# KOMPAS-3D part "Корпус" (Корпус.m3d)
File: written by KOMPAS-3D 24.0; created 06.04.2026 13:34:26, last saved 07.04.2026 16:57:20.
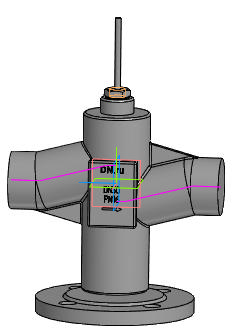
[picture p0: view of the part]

Document properties: Автор: R2D2; Полное имя файла: E:\Работа\Зайцев\Солянка\VSR1-13V-PED-F Клапан запорно-регулирующий DN.ru\DN50\исходные материалы\Корпус.m3d

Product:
- Body: Труба / Нестандартная труба / L = 112.5 мм  | qty 1
    Материал: Нестандартная труба (density 7856 kg/m3)
    Масса: 9.621901
    Раздел спецификации: Детали
    Примечание: 2,5 кг
    additional columns: Pipeline; 0.06; 0; 0; 0.002; 0.11245; true; 0.04
- Body: Труба / Нестандартная труба / L = 112.5 мм  | qty 1
    Материал: Нестандартная труба (density 7856 kg/m3)
    Масса: 9.621901
    Раздел спецификации: Детали
    Форматы листов документа: БЧ
    Примечание: 2,5 кг
    additional columns: Pipeline; 0.06; 0; 0; 0.002; 0.11245; true; 0.04
- Component [standard]: Гайка М16-6H ГОСТ 5916-70  | qty 1  | Масса: 0.01768; Рассекать на разрезах: no; source file: C:\Program Files\ASCON\KOMPAS-3D v24\Libs\PolynomLib\DATA\vault\Methods\Kompas\3D\PLib_Nut_OST92_900.m3d
- Component [standard]: (unnamed)  | qty 1  | Материал: ВЧ40 ГОСТ 7293-85 (density 7200 kg/m3); Масса: 2.386453; Рассекать на разрезах: no; additional columns: 50-16-B-2-ВЧ40-II; Заглушка; ГОСТ 34785-2021
- Body: Тело 4  | qty 1
    Материал: Нестандартная труба (density 7856 kg/m3)
    Масса: 9.621901
- Part/product: Корпус
    Масса: 6.9

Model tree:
1. Эскиз:1
2. Труба:1  (labels: {F703FF30-5BE6-4673-A7F1-8EDA1BE1E2D1}; SHAPEOBJECT3D_ATTR_BUTT; SHAPEOBJECT3D_ATTR_VALID; SHAPEOBJECT3D_ATTR_BUTT_AREA)
     PIPE_R = 7
3. Труба:2  (labels: {F703FF30-5BE6-4673-A7F1-8EDA1BE1E2D1}; SHAPEOBJECT3D_ATTR_BUTT; SHAPEOBJECT3D_ATTR_VALID; SHAPEOBJECT3D_ATTR_BUTT_AREA)
     PIPE_R = 7
4. Эскиз:2
5. Элемент выдавливания:1
     Расстояние 1 = 91; Смещение 1 = -1; Расстояние 2 = 112; Смещение 2 = -5
6. РЕБРО  (with: Ребро.Труба:1, Грань.Элемент выдавливания:1, Грань.Труба:1, Грань.Труба:2)
7. Элемент выдавливания:2
     Расстояние 1 = 6
8. Эскиз:4  (with: Грань.Элемент выдавливания:1)
9. Скругление:3  (with: Ребро.Элемент выдавливания:2)
10. Элемент выдавливания:3
     Расстояние 1 = 1
11. Эскиз:5  (with: Грань.Элемент выдавливания:3)
12. Элемент выдавливания:4
     Расстояние 1 = 7.5; Смещение 1 = 0.5
13. ШТОК
14. Элемент выдавливания:5
15. ОТЛИВКА
16. Скругление:6  (with: Грань.Элемент выдавливания:1)
17. Элемент выдавливания:6  (with: Грань.Элемент выдавливания:1)
     Смещение 1 = 4
18. Эскиз:8  (with: Грань.Элемент выдавливания:6)
19. Элемент выдавливания:7
     Расстояние 1 = 0.5
20. Скругление:7  (with: Ребро.Элемент выдавливания:6)
     Радиус = 2
21. Эскиз:9  (with: Грань.Элемент выдавливания:1, Ребро.Скругление:6, Ребро.Элемент выдавливания:5)
22. Элемент вращения:1
     Угол 1 = 360
23. Скругление:8  (with: Ребро.Элемент вращения:1, Грань.Элемент выдавливания:3)
     Радиус = 2

Expressions: DS/2+3; v22*2
Referenced files in C:\Program Files\ASCON\KOMPAS-3D v24\Libs\Pipeline\: StylesTemplate.a3d, TemplateHPH, InsulationStylesTemplate.a3d, Insulation
Referenced files in C:\Program Files\ASCON\KOMPAS-3D v24\Templates\: Констр. чертеж А3 гориз. перв. лист.cdt
Referenced files in E:\Работа\Зайцев\Солянка\VSR1-13V-PED-F Клапан запорно-регулирующий DN.ru\DN15\DN15 Kv0.16\исходные материалы\: 
Referenced files in C:\Program Files\ASCON\KOMPAS-3D v24\Libs\PolynomLib\DATA\vault\Methods\Kompas\3D\: PLib_Nut_OST92_900.m3d, PLib_Flange_Blind_GOST_34785_2100.m3d
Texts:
  Отводы ГОСТ 17375-2001
  Констр. чертеж А3 гориз. перв. лист.cdt
  BOSimple***PART:2c8e7818-1586-f79e-db7d-bc045ba468e4***SHORTLOC:Root±30±10±20±©{}110±10±50±80[Нет;Без покрытия;Без указания материала;-;16;2;24]
  BOSimple***Material:38d6725a-5efe-48e1-b177-a7817acb862a
  BOSimple***PART:6ce3b590-65f7-6eb6-bb7d-3d9c5ed0b677***SHORTLOC:B619_EF039B503CC34112[2;16;50;Круглая;II;ВЧ40 ГОСТ 7293-85]
  var3D
  GOST 2.304 type A
  PN16
  LL-10
  DN+10
  bcut1
  hole1
  hcut1
  hole2
  cut1
  Труба / Нестандартная труба / L = %s мм
  Plane. Начало координат
  Ось Y.Начало координат
  Плоскость ZX.Начало координат
  Плоскость ZY.Начало координат
  Горизонтальная плоскость. Начало координат
  Плоскость XY.Начало координат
